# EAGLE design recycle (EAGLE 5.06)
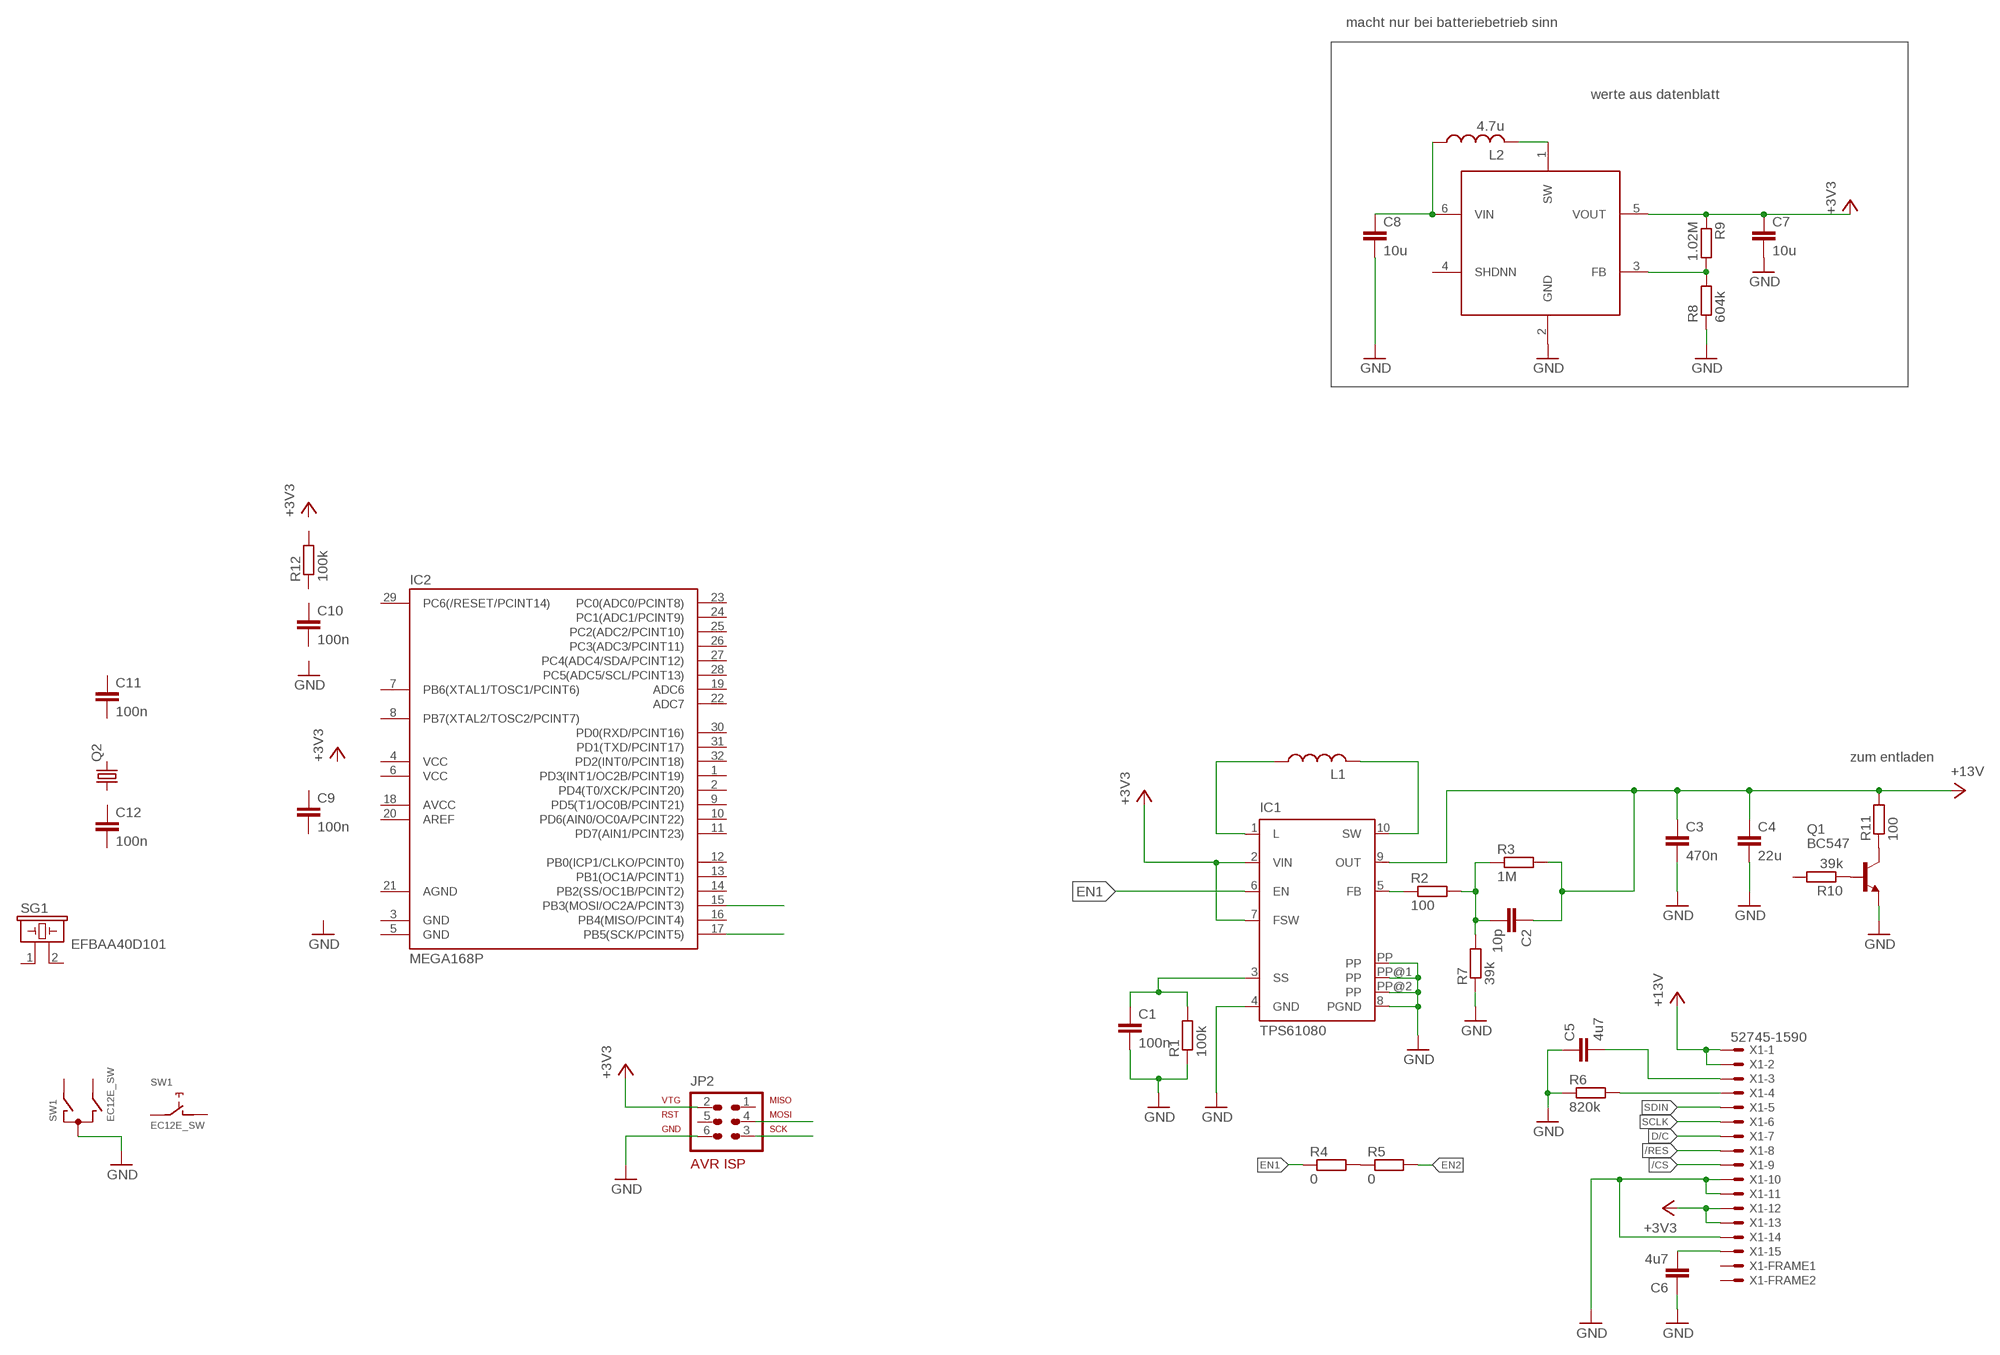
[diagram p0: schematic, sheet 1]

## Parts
C1  100n  C-EUC0603K  [C0603K]
C2  10p  C-EUC0402K  [C0402K]
C3  470n  C-EUC0603K  [C0603K]
C4  22u  C-EUC1206K  [C1206K]
C5  4u7  C-EUC0805  [C0805]
C6  4u7  C-EUC0805  [C0805]
C7  10u  C-EUC0603K  [C0603K]
C8  10u  C-EUC0603K  [C0603K]
C9  100n  C-EUC0603K  [C0603K]
C10  100n  C-EUC0603K  [C0603K]
C11  100n  C-EUC0603K  [C0603K]
C12  100n  C-EUC0603K  [C0603K]
IC1  TPS61080  [S-PDSO-N10]
IC2  MEGA168P  MEGA48/88/168-MU  [MLF32]
JP2  AVR-ISP-6  [AVR-ISP-6]
L1  L-USWE-TPC  [POWER-CHOKE_WE-TPC]
L2  4.7u  L-USWE-TPC  [POWER-CHOKE_WE-TPC]
Q1  BC547  [TO92]
Q2  CRYSTALHC49UP  [HC49UP]
R1  100k  R-EU_R0402  [R0402]
R2  100  R-EU_R0603  [R0603]
R3  1M  R-EU_R0402  [R0402]
R4  0  R-EU_R0603  [R0603]
R5  0  R-EU_R0603  [R0603]
R6  820k  R-EU_R0402  [R0402]
R7  39k  R-EU_R0402  [R0402]
R8  604k  R-EU_R0402  [R0402]
R9  1.02M  R-EU_R0402  [R0402]
R10  39k  R-EU_R0402  [R0402]
R11  100  R-EU_R0402  [R0402]
R12  100k  R-EU_R0402  [R0402]
SG1  EFBAA40D101  [EFBAA40D101]
SW1  EC12E_SW  [ALPS_EC12E_SW]
U$1  AS1329  [TSOT-236]
X1  52745-1590  [52745-1590]

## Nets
+3V3: IC1.2(VIN) IC1.7(FSW) X1.12 X1.13
+13: C2.1 C3.1 C4.1 IC1.9(OUT) R3.2 R11.2 X1.1 X1.2 ; supply symbol labelled +13V
/CS: X1.9
/RES: X1.8
D/C: X1.7
EN1: IC1.6(EN) R4.1
EN2: R5.2
GND: C1.2 C3.2 C4.2 C5.1 C6.1 C7.2 C8.2 IC1.4(GND) IC1.8(PGND) IC1.PP IC1.PP@1(PP) IC1.PP@2(PP) JP2.6 Q1.1(E) R1.1 R6.1 R7.1 R8.1 SW1.C U$1.2(GND) X1.10 X1.11 X1.14
N$1: IC1.1(L) L1.1
N$2: IC1.10(SW) L1.2
N$3: C1.1 IC1.3(SS) R1.2
N$4: C2.2 R2.2 R3.1 R7.2
N$5: IC1.5(FB) R2.1
N$6: R4.2 R5.1
N$7: R6.2 X1.4
N$8: C6.2 X1.15
N$9: C5.2 X1.3
N$10: JP2.3
N$11: JP2.4
N$12: R8.2 R9.2 U$1.3(FB)
N$13: L2.2 U$1.1(SW)
N$14: C8.1 L2.1 U$1.6(VIN)
N$15: Q1.3(C) R11.1
N$16: Q1.2(B) R10.1
N$17: IC2.17(PB5(SCK/PCINT5))
N$18: IC2.15(PB3(MOSI/OC2A/PCINT3))
SCLK: X1.6
SDIN: X1.5
VCC: C7.1 JP2.2 R9.1 U$1.5(VOUT) ; supply symbol labelled +3V3
Unconnected: C9.1 C9.2 C10.1 C10.2 C11.1 C11.2 C12.1 C12.2 IC2.1(PD3(INT1/OC2B/PCINT19)) IC2.2(PD4(T0/XCK/PCINT20)) IC2.7(PB6(XTAL1/TOSC1/PCINT6)) IC2.8(PB7(XTAL2/TOSC2/PCINT7)) IC2.9(PD5(T1/OC0B/PCINT21)) IC2.10(PD6(AIN0/OC0A/PCINT22)) IC2.11(PD7(AIN1/PCINT23)) IC2.12(PB0(ICP1/CLKO/PCINT0)) IC2.13(PB1(OC1A/PCINT1)) IC2.14(PB2(SS/OC1B/PCINT2)) IC2.16(PB4(MISO/PCINT4)) IC2.18(AVCC) IC2.19(ADC6) IC2.20(AREF) IC2.22(ADC7) IC2.23(PC0(ADC0/PCINT8)) IC2.24(PC1(ADC1/PCINT9)) IC2.25(PC2(ADC2/PCINT10)) IC2.26(PC3(ADC3/PCINT11)) IC2.27(PC4(ADC4/SDA/PCINT12)) IC2.28(PC5(ADC5/SCL/PCINT13)) IC2.29(PC6(/RESET/PCINT14)) IC2.30(PD0(RXD/PCINT16)) IC2.31(PD1(TXD/PCINT17)) IC2.32(PD2(INT0/PCINT18)) JP2.1 JP2.5 Q2.1 Q2.2 R10.2 R12.1 R12.2 SG1.1 SG1.2 SW1.A SW1.B SW1.D SW1.E SW1.GND1(G) SW1.GND2(G) U$1.4(SHDNN) X1.F1 X1.F2

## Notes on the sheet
- macht nur bei batteriebetrieb sinn
- werte aus datenblatt
- zum entladen

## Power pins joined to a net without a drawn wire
+3V3: IC2.4(VCC) IC2.6(VCC)
AGND: IC2.21(AGND)
GND: IC2.3(GND) IC2.5(GND)

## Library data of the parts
C1-C12 = rcl:C-EU: CAPACITOR, European symbol
IC1 = mystuff:TPS6108*: HIGH VOLTAGE DC/DC BOOST CONVERTER WITH 0.5-A/1.3-A INTEGRATED SWITCH Source: http://focus.ti.com/lit/ds/symlink/tps61080.pdf
IC2 = avr-6:MEGA48/88/168
JP2 = avr-6:AVR-ISP-6: AVR ISP-6 Serial Programming Header
L1 L2 = rcl:L-US: INDUCTOR, American symbol
Q1 = transistor-npn:BC547*: NPN Transistor
Q2 = crystal:CRYSTAL: CRYSTAL
R1-R12 = rcl:R-EU_: RESISTOR, European symbol
SG1 = buzzer:EFB?: Piezoelectric Acoustic Transducer
SW1 = switch-alps:EC12E_SW: ALPS rotary Encoder EC12E series with switch
U$1 = AS1329:AS1329
X1 = mystuff:52745-1590: FFC/FPC-to-Board 0.50mm (.020") SMT Top Contact Right Angle, ZIF, Style Receptacle 52745 / 52435 Source: http://www.molex.com/product/ffc/52745.html

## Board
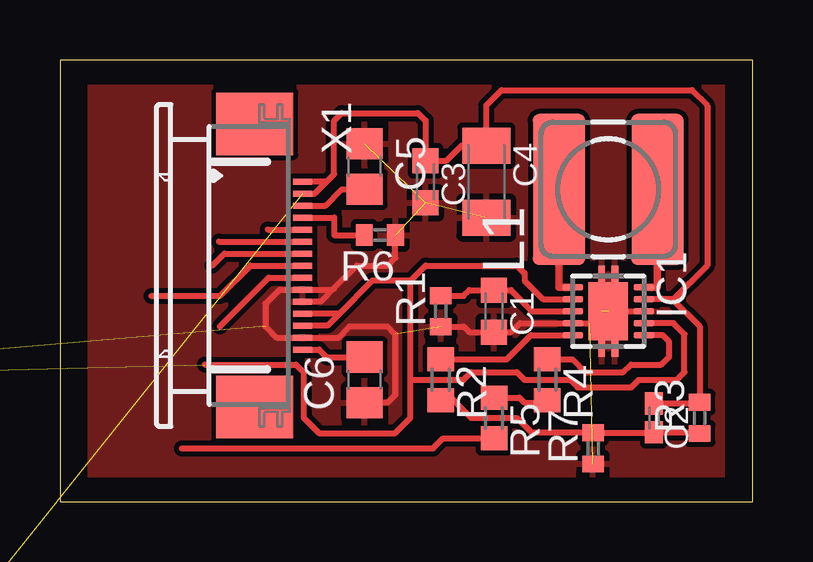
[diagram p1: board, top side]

Size 28.88 x 18.41 mm. Coordinates in mm from the lower left corner, seen from the top.
Outline: 0,0 28.88,0 28.88,18.41 0,18.41 0,0
Copper layers (1*16): Top 0.035mm / dielectric 1.5mm / Bottom 0.035mm
Design rules "default": minimum track width 10mil, minimum drill 24mil, track to track 8mil, track to pad 8mil, pad to pad 8mil, via to via 8mil, smd to smd 8mil, copper to edge 40mil, drill to drill 8mil, minimum pad ring 10mil, minimum via ring 8mil, stop-mask expansion 4mil, vias tented up to drill 0mil, thermal gap 10mil

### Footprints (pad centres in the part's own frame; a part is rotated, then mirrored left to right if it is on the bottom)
C0603K = smd 1.05 x 1.08: 1 -0.875,0; 2 0.875,0
C0402K = smd 0.925 x 0.74: 1 -0.6,0; 2 0.6,0
C1206K = smd 1.5 x 2: 1 -1.5,0; 2 1.5,0
C0805 = smd 1.3 x 1.5: 1 -0.95,0; 2 0.95,0
S-PDSO-N10 = smd 0.28 x 0.85: 1 -1,-1.475; 2 -0.5,-1.475; 3 0,-1.475; 4 0.5,-1.475; 5 1,-1.475; 6 1,1.475; 7 0.5,1.475; 8 0,1.475; 9 -0.5,1.475; 10 -1,1.475 | smd 2.4 x 1.65: PP 0,0 | smd 3.8 x 0.28: PP@1 0,0.275; PP@2 0,-0.275
MLF32 = smd 0.7 x 0.3: 1 -2.35,1.75; 2 -2.35,1.25; 3 -2.35,0.75; 4 -2.35,0.25; 5 -2.35,-0.25; 6 -2.35,-0.75; 7 -2.35,-1.25; 8 -2.35,-1.75; 17 2.35,-1.75; 18 2.35,-1.25; 19 2.35,-0.75; 20 2.35,-0.25; 21 2.35,0.25; 22 2.35,0.75; 23 2.35,1.25; 24 2.35,1.75 | smd 0.3 x 0.7: 9 -1.75,-2.35; 10 -1.25,-2.35; 11 -0.75,-2.35; 12 -0.25,-2.35; 13 0.25,-2.35; 14 0.75,-2.35; 15 1.25,-2.35; 16 1.75,-2.35; 25 1.75,2.35; 26 1.25,2.35; 27 0.75,2.35; 28 0.25,2.35; 29 -0.25,2.35; 30 -0.75,2.35; 31 -1.25,2.35; 32 -1.75,2.35
AVR-ISP-6 = drill 1.016 square: 1 -2.54,-1.27 | drill 1.016 octagon: 2 -2.54,1.27; 3 0,-1.27; 4 0,1.27; 5 2.54,-1.27; 6 2.54,1.27
POWER-CHOKE_WE-TPC = smd 6.3 x 2.2: 1 0,2.05; 2 0,-2.05
TO92 = drill 0.813 octagon: 1 1.27,0; 2 0,1.905; 3 -1.27,0
HC49UP = smd 5.334 x 1.93: 1 -4.826,0; 2 4.826,0
R0402 = smd 0.7 x 0.9: 1 -0.65,0; 2 0.65,0
R0603 = smd 1 x 1.1: 1 -0.85,0; 2 0.85,0
EFBAA40D101 = drill 1.1 pad 1.676 round: 1 -5,0; 2 5,0
ALPS_EC12E_SW = drill 1 square: A -2.5,-7.5; B 2.5,-7.5; C 0,-7.5; D -2.5,7; E 2.5,7 | drill 2.2 square: GND1 -6.1,0; GND2 6.1,0
TSOT-236 = smd 0.6 x 0.9: 1 -0.95,-1.15; 2 0,-1.15; 3 0.95,-1.15; 4 0.95,1.15; 5 0,1.15; 6 -0.95,1.15
52745-1590 = smd 0.25 x 0.8: 1 -3.5,2.5; 2 -3,2.5; 3 -2.5,2.5; 4 -2,2.5; 5 -1.5,2.5; 6 -1,2.5; 7 -0.5,2.5; 8 0,2.5; 9 0.5,2.5; 10 1,2.5; 11 1.5,2.5; 12 2,2.5; 13 2.5,2.5; 14 3,2.5; 15 3.5,2.5 | smd 2.6 x 3.2: F1 -5.9,0.5; F2 5.9,0.5

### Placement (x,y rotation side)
C1  18.1,7.94 270 top
C2  24.77,3.49 270 top
C3  15.24,13.33 270 top
C4  17.78,13.33 270 top
C5  12.7,13.97 270 top
C6  12.7,5.08 90 top
C7  not placed on the board
C8  not placed on the board
C9  not placed on the board
C10  not placed on the board
C11  not placed on the board
C12  not placed on the board
IC1  22.86,7.94 270 top
IC2  not placed on the board
JP2  not placed on the board
L1  22.86,13.02 90 top
L2  not placed on the board
Q1  not placed on the board
Q2  not placed on the board
R1  15.88,7.94 90 top
R2  15.88,5.08 270 top
R3  26.67,3.49 90 top
R4  20.32,5.08 270 top
R5  18.1,3.49 270 top
R6  13.33,11.11 180 top
R7  22.22,2.22 90 top
R8  not placed on the board
R9  not placed on the board
R10  not placed on the board
R11  not placed on the board
R12  not placed on the board
SG1  not placed on the board
SW1  not placed on the board
U$1  not placed on the board
X1  7.62,9.84 270 top

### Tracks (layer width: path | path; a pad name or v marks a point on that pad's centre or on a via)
+3V3  (2 unrouted)
  Top 0.254: IC1.2 20.14,8.44 19.37,9.21 19.37,9.53 19.05,9.84 15.24,9.84 14.61,9.21 | IC1.7 25.58,7.44 26.04,6.98 26.04,5.4 25.72,5.08 24.13,5.08 23.81,4.76 21.59,4.76 21.27,5.08 19.37,5.08 19.05,5.4 17.14,5.4 16.83,5.08 14.61,5.08 | 6.03,5.71 9.84,5.71 10.16,5.4 10.16,3.49 10.79,2.86 13.97,2.86 14.61,3.49 14.61,5.08 | 14.61,5.08 14.61,9.21 | 11.65,7.84 X1.12 | 11.65,7.84 13.02,9.21 14.61,9.21 | X1.13 11.15,7.34 11.65,7.84
+13  (1 unrouted)
  Top 0.254: 25.54,8.44 IC1.9 | 25.54,8.44 26.67,7.3 R3.2 26.62,4.09 C2.1 | 25.54,8.44 25.58,8.44 26.99,9.84 26.99,16.51 26.35,17.14 18.41,17.14 17.78,16.51 C4.1 16.74,14.83 16.12,14.21 C3.1 15.24,15.88 14.92,16.19 11.75,16.19 11.43,15.88 11.43,13.65 11.12,13.34 | 11.12,13.34 X1.1 | X1.2 10.62,12.84 11.12,13.34
/CS
  Top 0.254: X1.9 8.71,9.34 6.67,7.3
/RES
  Top 0.254: X1.8 7.94,9.84 6.67,8.57 3.81,8.57
D/C
  Top 0.254: X1.7 6.85,10.34 6.35,9.84
EN1
  Top 0.254: IC1.6 25.13,6.94 25.4,6.67 25.4,6.03 25.08,5.71 23.81,5.71 23.5,5.4 21.91,5.4 21.38,5.93 R4.1
EN2
  Top 0.254: R5.2 15.98,2.64 15.56,2.22 5.08,2.22
GND  (15 unrouted)
  Top 0.254: IC1.PP@2 22.09,7.44 IC1.4 19.18,7.44 18.81,7.06 C1.2 17.07,7.06 16.83,7.3 16.81,7.29 R1.1 | IC1.8 IC1.PP@1 IC1.PP | 8.57,8.26 8.57,7.3 9.03,6.84 X1.14 11.61,6.84 12.06,7.3 13.65,7.3 13.97,6.98 13.97,4.45 13.65,4.13 C6.1 | 8.57,8.26 9.16,8.84 X1.10 11.38,8.84 11.43,8.89 | 8.66,8.34 8.57,8.26 | X1.11 10.88,8.34 11.43,8.89 | 11.43,8.89 12.38,9.84 13.65,9.84 13.97,10.16 13.97,11.1 R6.1
  pour Top: 1.27,0.64 27.62,0.64 27.62,17.78 1.27,17.78
N$1
  Top 0.305: IC1.1 20.81,8.94 L1.1
N$2
  Top 0.305: IC1.10 24.91,8.94 L1.2
N$3
  Top 0.254: R1.2 16.81,8.59 16.83,8.57 17.07,8.81 C1.1 18.81,8.81 19.68,7.94 IC1.3
N$4
  Top 0.254: R2.2 16.41,4.23 17.14,3.49 19.05,3.49 19.65,2.89 22.22,2.89 | 26.66,2.86 R3.1 26.62,2.89 C2.2 | R7.2 24.77,2.87
  Top 0.406: 22.22,2.89 R7.2 | 24.77,2.87 C2.2
N$5
  Top 0.254: IC1.5 19.64,6.94 18.63,5.93 R2.1
N$6
  Top 0.254: R5.1 19.15,4.34 19.37,4.13 20.22,4.13 R4.2
N$7
  Top 0.254: R6.2 11.43,11.11 11.43,11.84 X1.4
N$8
  Top 0.254: X1.15 10.8,6.34 11.12,6.03 C6.2
N$9
  Top 0.254: 13.01,13.02 C5.2 11.75,13.02 11.07,12.34 X1.3
N$12  (2 unrouted)
N$13  (1 unrouted)
N$14  (2 unrouted)
N$15  (1 unrouted)
N$16  (1 unrouted)
SCLK
  Top 0.254: 6.62,10.84 X1.6
SDIN
  Top 0.254: 8.66,11.34 X1.5
VCC  (3 unrouted)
